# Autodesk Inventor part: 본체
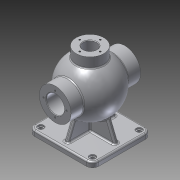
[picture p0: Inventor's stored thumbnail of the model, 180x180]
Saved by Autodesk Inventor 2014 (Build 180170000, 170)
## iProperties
Created: 2015-10
Part Number: 본체
Material: 알루미늄 6061
Document SubType Name: Modeling
Designer: youjin22
Density: 2.71 g/cm^3
Appearance: 알루미늄 - 평지
Mass: 1509.55 g
Surface Area: 1153.76 cm^2
Volume: 557.03 cm^3
Author: youjin22
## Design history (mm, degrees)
sketch "스케치1"
  geometry: L1 (-50.5, 57.5)-(50.5, 57.5); L2 (62.5, 45.5)-(62.5, -45.5); L3 (50.5, -57.5)-(-50.5, -57.5); L4 (-62.5, -45.5)-(-62.5, 45.5); L5 (-62.5, 57.5)-(62.5, -57.5); L6 (62.5, 57.5)-(-62.5, -57.5); A1 r 12 centre (-50.5, 45.5) between (-50.5, 57.5) and (-62.5, 45.5); A2 r 12 centre (50.5, 45.5) between (62.5, 45.5) and (50.5, 57.5); A3 r 12 centre (50.5, -45.5) between (50.5, -57.5) and (62.5, -45.5); A4 r 12 centre (-50.5, -45.5) between (-62.5, -45.5) and (-50.5, -57.5); 1 further point
  constraints: 12 end point, 8 point on circle, 8 point on line, 8 tangent, 4 centre point, 3 equal radius, 2 midpoint, 2 parallel, 1 horizontal, 1 perpendicular
  dimensions: "d0" = 125 distance of L5.end L6.end; "d1" = 115 distance of L6.start L5.end; "d2" = 12 radius of A1
extrude "돌출1" new body sketch "스케치1" distance "d3" = 10; taper "d4" = 0 deg
sketch "스케치2"
  geometry: L1 (0, 32)-(0, 138); A1 r 53 centre (0, 85) between (0, 32) and (0, 138); A2 r 53 centre (0, 85) between (0, 138) and (0, 32); 1 further point
  constraints: 4 point on circle, 2 centre point, 2 end point, 1 vertical, 1 vertical alignment
  dimensions: "d5" = 53 radius of A1; "d6" = 85 distance of A1.centre point (0, 0)
revolve "회전1" stored, may be unused: angle "d7" = 90 deg
sketch "스케치3"
  geometry: L1 (-50.5, 10)-(-62.5, 10) reference; L2 (62.5, 10)-(50.5, 10) reference; L3 (-52.5, 10)-(-37.379, 47.426); L4 (52.5, 10)-(37.379, 47.426); L5 (-62.5, 0)-(-62.5, 10) reference; L6 (62.5, 0)-(62.5, 10) reference; L7 (-52.5, 10)-(52.5, 10); L8 (-37.379, 47.426)-(37.379, 47.426); A1 r 53 centre (0, 85) between (-37.379, 47.426) and (37.379, 47.426) reference; 1 further point
  constraints: 8 end point, 2 point on circle, 2 point on line, 1 perpendicular
  dimensions: "d8" = 10 distance of L3.start L1.end; "d9" = 10 distance of L4.start L2.start; "d10" = 22 deg angle of L3 L5; "d11" = 22 deg angle of L4 L6
extrude "돌출2" join sketch "스케치3" stored distance "d12" = 8; taper "d13" = 0 deg
extrude "돌출10" join sketch "스케치3" stored distance "d96" = 8; taper "d97" = 0 deg
sketch "스케치4"
  geometry: L1 (-45.5, 10)-(-57.5, 10) reference; L2 (57.5, 10)-(45.5, 10) reference; L3 (-47.5, 10)-(-33.719, 44.109); L4 (47.5, 10)-(33.719, 44.109); L5 (57.5, 0)-(57.5, 10) reference; L6 (-57.5, 0)-(-57.5, 10) reference; L7 (-33.719, 44.109)-(33.719, 44.109); A1 r 53 centre (0, 85) between (-33.719, 44.109) and (33.719, 44.109) reference; 1 further point
  constraints: 6 end point, 2 point on circle, 2 point on line
  dimensions: "d14" = 10 distance of L3.start L1.end; "d15" = 10 distance of L4.start L2.start; "d16" = 22 deg angle of L4 L5; "d17" = 22 deg angle of L3 L6
feature "리브1" dims "d18" = 1, "d19" = 8, "d20" = 0, "d21" = 0, "d22" = 1, "d23" = 1
feature "리브2" dims "d24" = 1, "d25" = 8, "d26" = 0, "d27" = 0, "d28" = 1, "d29" = 1
node "작업 평면1"
sketch "스케치5"
  geometry: C1 r 27 at (0, 0); 1 further point
  constraints: 1 centre point, 1 coincident
  dimensions: "d31" = 54 diameter of C1
extrude "돌출3" join sketch "스케치5" stored distance "d32" = 8; taper "d33" = 0 deg
node "작업 평면2"
sketch "스케치6"
  geometry: C1 r 31 at (0, 85); 1 further point
  constraints: 1 centre point, 1 vertical alignment
  dimensions: "d35" = 62 diameter of C1; "d36" = 85 distance of point (0, 0) C1.centre
extrude "돌출4" join sketch "스케치6" distance "d37" = 136; taper "d38" = 0 deg
sketch "스케치7"
  geometry: L1 (0, 128)-(0, 42); A1 r 53 centre (0, 85) between (0, 138) and (0, 32) reference; A2 r 43 centre (0, 85) between (0, 128) and (0, 42); 1 further point
  constraints: 2 end point, 2 point on circle, 2 vertical alignment, 1 centre point, 1 coincident, 1 vertical
  dimensions: "d39" = 43 radius of A2
revolve "회전2" sketch "스케치7" stored, may be unused: angle "d40" = 90 deg
sketch "스케치8"
  geometry: C1 r 27 at (0, 0) reference; C2 r 13 at (0, 0)
  constraints: 1 centre point, 1 coincident
  dimensions: "d41" = 26 diameter of C2
extrude "돌출5" cut sketch "스케치8" stored distance "d42" = 136; taper "d43" = 0 deg
sketch "스케치9"
  geometry: C1 r 31 at (0, 0) reference; C2 r 17.5 at (0, 0); 1 further point
  constraints: 1 centre point, 1 coincident
  dimensions: "d44" = 35 diameter of C2
extrude "돌출6" cut sketch "스케치9" stored distance "d45" = 136; taper "d46" = 0 deg
sketch "스케치10"
  geometry: C1 r 31 at (0, 0) reference; C2 r 17.5 at (0, 0); 1 further point
  constraints: 1 centre point, 1 coincident
  dimensions: "d47" = 35 diameter of C2
extrude "돌출7" cut sketch "스케치10" distance "d48" = 16; taper "d49" = 0 deg
sketch "스케치11"
  geometry: C1 r 17.5 at (0, 0) reference; C2 r 18.5 at (0, 0); 1 further point
  constraints: 1 centre point, 1 coincident
  dimensions: "d50" = 37 diameter of C2
extrude "돌출8" cut sketch "스케치11" distance "d51" = 1.75; taper "d52" = 0 deg
sketch "스케치12"
  geometry: C1 r 18.5 at (0, 0) reference; C2 r 17.5 at (0, 0); 1 further point
  constraints: 1 centre point, 1 coincident
  dimensions: "d53" = 35 diameter of C2
extrude "돌출9" cut sketch "스케치12" stored distance "d54" = 1.75; taper "d55" = 0 deg
sketch "스케치13"
  geometry: C1 r 17.5 at (0, 0) reference; C2 r 31 at (0, 0) reference; A1 r 22.5 centre (0, 0) between (0, -22.5) and (22.5, 0); 3 further points
  constraints: 4 point on circle, 2 horizontal alignment, 2 vertical alignment, 1 centre point, 1 coincident
  dimensions: "d56" = 45 diameter of A1
hole "구멍1" sketch "스케치13" at (0, 22.5), (22.5, 0), (0, -22.5), (-22.5, 0) diameter "d57" = 3.242; stored, may be unused: countersink angle "d61" = 90 deg, drill point angle "d63" = 118 deg; dims "d58" = 12, "d59" = 4, "d60" = 2, "d62" = 15
sketch "스케치14"
  geometry: C1 r 17.5 at (0, 0) reference; C2 r 31 at (0, 0) reference; A1 r 24 centre (0, 0) between (0, -24) and (0, 24); 3 further points
  constraints: 4 point on circle, 2 horizontal alignment, 2 vertical alignment, 1 centre point, 1 coincident
  dimensions: "d64" = 48 diameter of A1
hole "구멍2" sketch "스케치14" at (0, 24), (-24, 0), (0, -24), (24, 0) diameter "d65" = 3.242; stored, may be unused: countersink angle "d69" = 90 deg, drill point angle "d71" = 118 deg; dims "d66" = 16, "d67" = 4, "d68" = 2, "d70" = 19
sketch "스케치15"
  geometry: C1 r 13 at (0, 0) reference; C2 r 27 at (0, 0) reference; A1 r 20 centre (0, 0) between (0, -20) and (-20, 0); 2 further points
  constraints: 4 point on circle, 2 horizontal alignment, 2 vertical alignment, 1 centre point, 1 coincident
  dimensions: "d72" = 40 diameter of A1
hole "구멍3" sketch "스케치15" at (0, 20), (-20, 0), (0, -20), (20, 0) diameter "d73" = 3.242; stored, may be unused: countersink angle "d77" = 90 deg, drill point angle "d79" = 118 deg; dims "d74" = 9, "d75" = 4, "d76" = 2, "d78" = 11
chamfer "모따기1" distance "d80" = 1; stored, may be unused: second distance "d81" = 2, angle "d82" = 45 deg
node "작업 평면3"
sketch "스케치16"
  geometry: L1 (-27, 0)-(27, 0) reference; 2 further points
  constraints: 1 vertical alignment, 1 other
  dimensions: "d83" = 10 distance from line of point (0, -10) L1
feature "엠보싱1" sketch "스케치16" dims "d84" = 0.5, "d85" = 0
sketch "스케치17"
  geometry: A1 r 12 centre (50.5, -45.5) between (50.5, -57.5) and (62.5, -45.5) reference; A2 r 12 centre (50.5, 45.5) between (62.5, 45.5) and (50.5, 57.5) reference; A3 r 12 centre (-50.5, 45.5) between (-50.5, 57.5) and (-62.5, 45.5) reference; A4 r 12 centre (-50.5, -45.5) between (-62.5, -45.5) and (-50.5, -57.5) reference; 5 further points
  constraints: 4 coincident
hole "구멍4" sketch "스케치17" at (-50.5, 45.5), (50.5, 45.5), (50.5, -45.5), (-50.5, -45.5) diameter "d86" = 8; stored, may be unused: countersink angle "d90" = 90 deg, drill point angle "d92" = 0 deg; dims "d87" = 9, "d88" = 12, "d89" = 3, "d91" = 10
fillet "모깎기1" dims "d93" = 3
fillet "모깎기4" dims "d98" = 3
fillet "모깎기5" dims "d99" = 3
fillet "모깎기6" dims "d100" = 3
fillet "모깎기7" dims "d101" = 3
node "솔리드1"
other parameters: "d34" = -68
